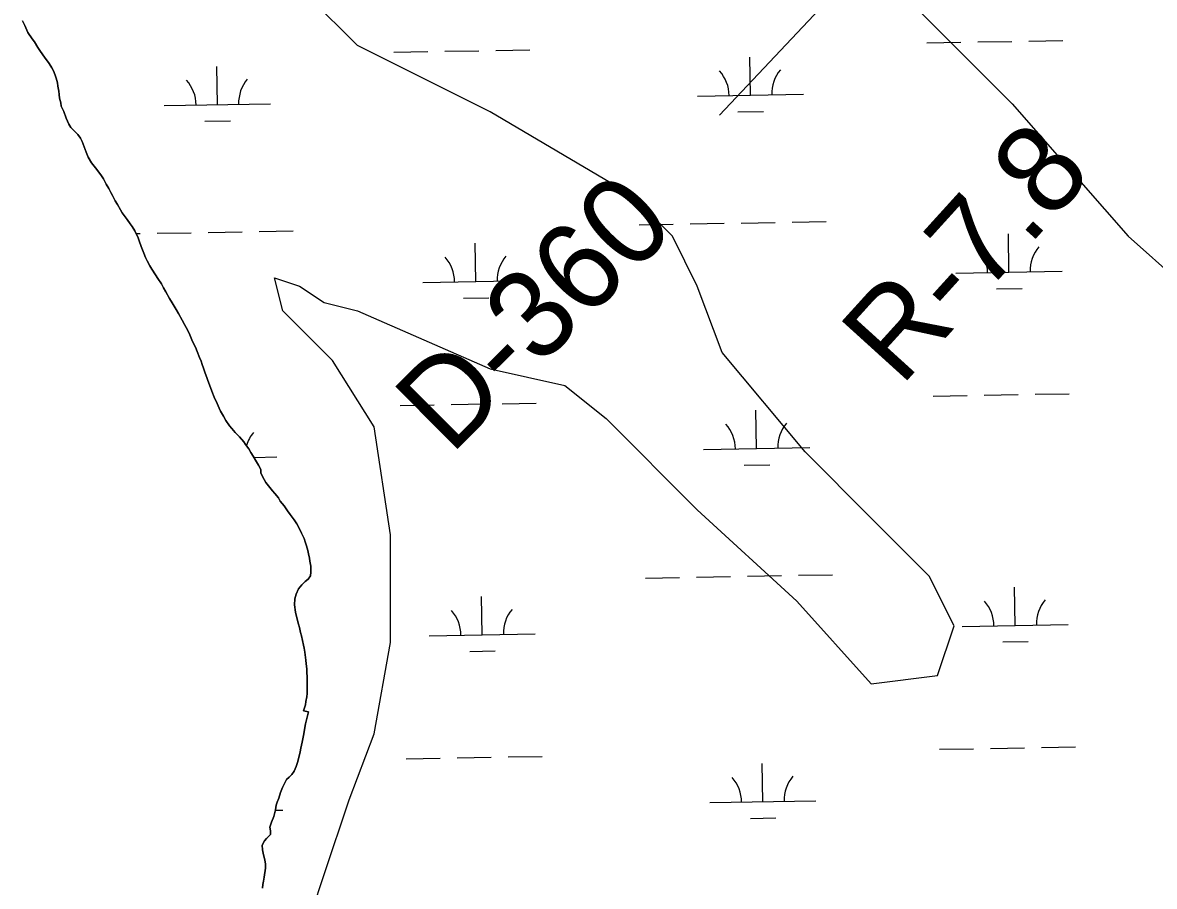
# Model space of a CAD drawing. Extents: x 3903937 to 3942190, y 260677 to 286651.
# Drawn here: x 3922685 to 3923750, y 276234 to 277048 of the extents above; entities that cross this region are included whole.
import ezdxf

# ---------------------------------------------------------------- set-up
doc = ezdxf.new("R2010")
doc.units = 0
for name, color, linetype in [('V-RIVR-RANG', 7, 'Continuous'), ('V-RIVR-RANG-IDEN', 7, 'Continuous'), ('V-SITE-VEGE', 7, 'Continuous'), ('V-TOPO-SHOR', 7, 'Continuous'), ('V-WETL-SWMP', 7, 'Continuous')]:
    doc.layers.add(name, color=color, linetype=linetype)

msp = doc.modelspace()

# ---------------------------------------------------------------- linework, layer by layer
at = {"layer": 'V-RIVR-RANG'}
msp.add_line((3923341.1, 276960.6), (3923889, 277543.5), dxfattribs=at)
at = {"layer": 'V-SITE-VEGE'}
for p, q in [((3923484, 277104.3), (3923616.6, 276971.5)), ((3923000.2, 277026.2), (3922930, 277096.5)), ((3923125.1, 276963.7), (3923000.2, 277026.2)), ((3923257.7, 276885.7), (3923125.1, 276963.7)), ((3923616.6, 276971.5), (3923725.9, 276846.6)), ((3923296.7, 276846.6), (3923257.7, 276885.7)), ((3923320.1, 276799.8), (3923296.7, 276846.6)), ((3923725.9, 276846.6), (3923866.3, 276721.7)), ((3922930, 276776.4), (3922922.2, 276807.6)), ((3922922.2, 276807.6), (3922945.6, 276799.8)), ((3922945.6, 276799.8), (3922969, 276784.2)), ((3923343.5, 276737.3), (3923320.1, 276799.8)), ((3922969, 276784.2), (3923000.2, 276776.4)), ((3922976.8, 276729.5), (3922930, 276776.4)), ((3923000.2, 276776.4), (3923125.1, 276721.7)), ((3923015.8, 276667.1), (3922976.8, 276729.5)), ((3923421.6, 276643.7), (3923343.5, 276737.3)), ((3923125.1, 276721.7), (3923195.3, 276706.1)), ((3923195.3, 276706.1), (3923234.3, 276674.9)), ((3923234.3, 276674.9), (3923320.1, 276589)), ((3923031.4, 276565.6), (3923015.8, 276667.1)), ((3923484, 276581.2), (3923421.6, 276643.7)), ((3923320.1, 276589), (3923413.8, 276503.1)), ((3923538.6, 276526.6), (3923484, 276581.2)), ((3923031.4, 276464.1), (3923031.4, 276565.6)), ((3923562, 276479.7), (3923538.6, 276526.6)), ((3923413.8, 276503.1), (3923484, 276425.1)), ((3923546.4, 276432.9), (3923562, 276479.7)), ((3923015.8, 276378.2), (3923031.4, 276464.1)), ((3923484, 276425.1), (3923546.4, 276432.9)), ((3922992.4, 276315.8), (3923015.8, 276378.2)), ((3922969, 276245.5), (3922992.4, 276315.8)), ((3922945.6, 276175.2), (3922969, 276245.5))]:
    msp.add_line(p, q, dxfattribs=at)
at = {"layer": 'V-TOPO-SHOR'}
for points in [[(3922685, 277049.5), (3922687, 277045), (3922690, 277038.6)], [(3922690, 277038.6), (3922694, 277032.7), (3922696.1, 277029.6), (3922699.3, 277024.4), (3922701.8, 277020.7), (3922705.7, 277015.2), (3922710.1, 277009.4), (3922712.5, 277005.3), (3922714, 277002.5), (3922715.7, 276998.3), (3922716.7, 276995.5), (3922717.7, 276991), (3922718.1, 276988), (3922719.1, 276983.3), (3922719.4, 276980), (3922719.8, 276976.8), (3922720.8, 276972.4), (3922721.4, 276969), (3922723.7, 276964.1), (3922725.9, 276958), (3922728.4, 276952.2), (3922730.4, 276949.2), (3922734.1, 276945.3), (3922736.9, 276942.5), (3922739.6, 276938.9), (3922741.1, 276936), (3922742.9, 276931), (3922744.8, 276925.9), (3922746.8, 276921), (3922749.8, 276915.7), (3922754.8, 276909.5), (3922759.3, 276903.4), (3922761.2, 276900.8), (3922763.6, 276895.8), (3922766.2, 276891.6), (3922768.1, 276887.9), (3922769.5, 276885), (3922772.2, 276880), (3922774.2, 276876.6), (3922777, 276871.6), (3922778.8, 276868.6), (3922781.5, 276864.8), (3922783.3, 276862.3), (3922786.3, 276858.4), (3922788.2, 276855.8), (3922790.5, 276851.7), (3922792, 276848.9), (3922793.5, 276846.2), (3922794.8, 276842.4), (3922796.7, 276837.1), (3922799, 276830.6), (3922800.7, 276826.5), (3922802.2, 276823.6), (3922804.9, 276818.9), (3922806.7, 276815.7), (3922810.2, 276810.4), (3922812.4, 276807), (3922815.6, 276801.8), (3922817.7, 276798.1), (3922819.9, 276794.2), (3922823.3, 276788.1), (3922825.7, 276783.9), (3922829.4, 276777.8), (3922831.7, 276773.8), (3922835.3, 276767.6), (3922837.4, 276763.4), (3922840.4, 276757.9), (3922842.4, 276753.8), (3922845, 276747.5), (3922847.7, 276742.1), (3922849.4, 276738.1), (3922851.6, 276732.4), (3922853, 276728.9), (3922854.1, 276725.8), (3922855.4, 276722.3), (3922856.8, 276717.6), (3922858.3, 276713.7), (3922859.4, 276710.9), (3922861, 276706.7), (3922863.1, 276700.9), (3922865.2, 276695.1), (3922868, 276689.1), (3922870.1, 276684.8), (3922871.4, 276682), (3922874.2, 276677.1), (3922876.2, 276673.2), (3922879.7, 276668.1), (3922881.8, 276665.6), (3922885.2, 276661.8), (3922889.1, 276657.9), (3922893.1, 276653.2), (3922894.9, 276650.7), (3922897.9, 276646.4), (3922899.7, 276643), (3922901.9, 276639.5), (3922905.2, 276634.1), (3922907.2, 276631.1), (3922909.4, 276626.9), (3922909.4, 276623.9), (3922910.8, 276620.5), (3922913.9, 276614.9)], [(3922913.9, 276614.9), (3922916.4, 276611.5), (3922920.2, 276607), (3922922.4, 276604.5), (3922925.8, 276600.3), (3922927.6, 276597.3), (3922931.1, 276592.7), (3922934.5, 276588), (3922936.9, 276584.7), (3922940.6, 276579.5), (3922943.1, 276575.8), (3922946.1, 276570.5), (3922947.6, 276567.1), (3922949.9, 276562.1), (3922951.1, 276558.8), (3922952.3, 276555.2), (3922953.6, 276550.6), (3922954.1, 276547.6), (3922955, 276543.6), (3922955.5, 276540.6), (3922956.2, 276536.1), (3922956.3, 276530.3), (3922955.9, 276527), (3922953.7, 276523.8), (3922951, 276521.4), (3922947.9, 276518.4), (3922944.7, 276514.5), (3922942.4, 276509.7), (3922941.3, 276505.3), (3922941, 276499.5), (3922942, 276492.8), (3922942.9, 276488.6), (3922944.7, 276481.3), (3922945.6, 276478.3), (3922946.6, 276473.5), (3922947.5, 276470.3), (3922948.4, 276465.9), (3922949.5, 276461.7), (3922950.1, 276458.7), (3922950.8, 276455), (3922951.6, 276447.6), (3922952, 276444.1), (3922952.5, 276439.3), (3922952.7, 276436), (3922952.9, 276431.8), (3922952.9, 276425.8), (3922952.9, 276421.9), (3922952.9, 276416.2), (3922952.4, 276412.8), (3922951.7, 276408.5), (3922951.3, 276405.3), (3922949.5, 276399.9), (3922954, 276398.8), (3922952.7, 276392.5), (3922951.2, 276387.5), (3922950.7, 276384), (3922949.8, 276378.2), (3922948.1, 276370.3), (3922946.8, 276364.6), (3922946.2, 276361.1), (3922945.2, 276357), (3922943.8, 276351.1), (3922942.5, 276347.4), (3922940.6, 276343), (3922938.3, 276339.7), (3922936, 276337.4), (3922933.4, 276335), (3922931.6, 276331.4), (3922929.7, 276327.4), (3922927.7, 276322.7), (3922926.1, 276317.6), (3922924.7, 276313.8), (3922923.7, 276310.8), (3922923.1, 276306.6), (3922921.4, 276300.3), (3922919.3, 276294.9), (3922917.8, 276290.2), (3922918.5, 276286.6), (3922918.3, 276283.2), (3922914.7, 276279.5), (3922912.6, 276277.3), (3922910.6, 276273.3), (3922910.9, 276268.9), (3922911.9, 276264.3), (3922912.9, 276259.3), (3922913.6, 276255.4), (3922913.6, 276251.7), (3922912.5, 276243.1), (3922911.8, 276239.4), (3922911, 276236.2), (3922910.8, 276232.7)]]:
    msp.add_lwpolyline(points, dxfattribs=at)
at = {"layer": 'V-WETL-SWMP'}
for p, q in [((3922687, 277045), (3922685, 277049.5)), ((3922690, 277038.6), (3922687, 277045)), ((3922694, 277032.7), (3922690, 277038.6)), ((3922696.1, 277029.6), (3922694, 277032.7)), ((3922699.3, 277024.4), (3922696.1, 277029.6)), ((3923536.4, 277028.7), (3923568.4, 277029.3)), ((3923584.4, 277029.6), (3923616.4, 277030.2)), ((3923632.4, 277030.4), (3923664.3, 277031)), ((3922701.8, 277020.7), (3922699.3, 277024.4)), ((3922705.7, 277015.2), (3922701.8, 277020.7)), ((3922710.1, 277009.4), (3922705.7, 277015.2)), ((3923034.5, 277019.9), (3923066.5, 277020.5)), ((3923082.5, 277020.8), (3923114.5, 277021.3)), ((3923130.5, 277021.6), (3923162.5, 277022.2)), ((3923370.1, 276979.4), (3923369.5, 277015.4)), ((3922712.6, 277005.3), (3922710.1, 277009.4)), ((3922714, 277002.5), (3922712.6, 277005.3)), ((3922868.3, 276970.6), (3922867.7, 277006.5)), ((3922715.7, 276998.3), (3922714, 277002.5)), ((3922716.7, 276995.5), (3922715.7, 276998.3)), ((3922717.7, 276991), (3922716.7, 276995.5)), ((3922718.1, 276988), (3922717.7, 276991)), ((3922719.1, 276983.3), (3922718.1, 276988)), ((3922719.4, 276980), (3922719.1, 276983.3)), ((3922719.8, 276976.8), (3922719.4, 276980)), ((3922720.8, 276972.4), (3922719.8, 276976.8)), ((3922721.4, 276969), (3922720.8, 276972.4)), ((3923320.2, 276978.5), (3923420.1, 276980.3)), ((3922723.7, 276964.1), (3922721.4, 276969)), ((3922725.9, 276957.9), (3922723.7, 276964.1)), ((3922818.3, 276969.7), (3922918.3, 276971.4)), ((3923358.4, 276963.7), (3923382.4, 276964.2)), ((3922728.4, 276952.2), (3922725.9, 276957.9)), ((3922730.4, 276949.2), (3922728.4, 276952.2)), ((3922856.6, 276954.9), (3922880.6, 276955.3)), ((3922734.1, 276945.3), (3922730.4, 276949.2)), ((3922736.9, 276942.5), (3922734.1, 276945.3)), ((3922739.6, 276938.9), (3922736.9, 276942.5)), ((3922741.1, 276936), (3922739.6, 276938.9)), ((3922742.9, 276931), (3922741.1, 276936)), ((3922744.8, 276925.9), (3922742.9, 276931)), ((3922746.8, 276921), (3922744.8, 276925.9)), ((3922749.8, 276915.7), (3922746.8, 276921)), ((3922754.8, 276909.5), (3922749.8, 276915.7)), ((3922759.3, 276903.4), (3922754.8, 276909.5)), ((3922761.2, 276900.8), (3922759.3, 276903.4)), ((3922763.6, 276895.8), (3922761.2, 276900.8)), ((3922766.2, 276891.6), (3922763.6, 276895.8)), ((3922768.1, 276887.9), (3922766.2, 276891.6)), ((3922769.5, 276885), (3922768.1, 276887.9)), ((3922772.2, 276880), (3922769.5, 276885)), ((3922774.2, 276876.6), (3922772.2, 276880)), ((3922777, 276871.6), (3922774.2, 276876.6)), ((3922778.8, 276868.6), (3922777, 276871.6)), ((3922781.5, 276864.8), (3922778.8, 276868.6)), ((3922783.3, 276862.3), (3922781.5, 276864.8)), ((3922786.3, 276858.4), (3922783.3, 276862.3)), ((3922788.2, 276855.8), (3922786.3, 276858.4)), ((3922790.5, 276851.7), (3922788.2, 276855.8)), ((3923265.4, 276857.5), (3923297.4, 276858)), ((3923313.4, 276858.3), (3923345.4, 276858.9)), ((3923361.4, 276859.1), (3923393.4, 276859.7)), ((3923409.4, 276860), (3923441.4, 276860.6)), ((3922792, 276848.9), (3922790.5, 276851.7)), ((3922791.9, 276849.1), (3922795.6, 276849.2)), ((3922793.5, 276846.2), (3922792, 276848.9)), ((3922794.8, 276842.4), (3922793.5, 276846.2)), ((3922811.6, 276849.5), (3922843.6, 276850)), ((3922859.6, 276850.3), (3922891.6, 276850.9)), ((3922907.6, 276851.2), (3922939.6, 276851.7)), ((3923613.6, 276812.8), (3923613, 276848.8)), ((3922796.7, 276837.1), (3922794.8, 276842.4)), ((3922799, 276830.6), (3922796.7, 276837.1)), ((3923111.8, 276804), (3923111.1, 276840)), ((3922800.7, 276826.5), (3922799, 276830.6)), ((3922802.2, 276823.6), (3922800.7, 276826.5)), ((3922804.9, 276818.9), (3922802.2, 276823.6)), ((3922806.7, 276815.7), (3922804.9, 276818.9)), ((3922810.2, 276810.4), (3922806.7, 276815.7)), ((3923563.6, 276812), (3923663.6, 276813.7)), ((3922812.4, 276807), (3922810.2, 276810.4)), ((3922815.6, 276801.8), (3922812.4, 276807)), ((3922817.7, 276798.1), (3922815.6, 276801.8)), ((3923061.8, 276803.1), (3923161.7, 276804.9)), ((3922819.9, 276794.2), (3922817.7, 276798.1)), ((3922823.3, 276788.1), (3922819.9, 276794.2)), ((3923601.9, 276797.2), (3923625.9, 276797.6)), ((3922825.7, 276783.9), (3922823.3, 276788.1)), ((3922829.4, 276777.8), (3922825.7, 276783.9)), ((3923100, 276788.4), (3923124, 276788.8)), ((3922831.7, 276773.8), (3922829.4, 276777.8)), ((3922835.3, 276767.6), (3922831.7, 276773.8)), ((3922837.4, 276763.4), (3922835.3, 276767.6)), ((3922840.4, 276757.9), (3922837.4, 276763.4)), ((3922842.4, 276753.8), (3922840.4, 276757.9)), ((3922845, 276747.5), (3922842.4, 276753.8)), ((3922847.7, 276742.1), (3922845, 276747.5)), ((3922849.4, 276738.1), (3922847.7, 276742.1)), ((3922851.6, 276732.4), (3922849.4, 276738.1)), ((3922853, 276728.9), (3922851.6, 276732.4)), ((3922854.1, 276725.8), (3922853, 276728.9)), ((3922855.4, 276722.3), (3922854.1, 276725.8)), ((3922856.8, 276717.6), (3922855.4, 276722.3)), ((3922858.3, 276713.7), (3922856.8, 276717.6)), ((3922859.4, 276710.9), (3922858.3, 276713.7)), ((3922861, 276706.7), (3922859.4, 276710.9)), ((3922863.1, 276700.9), (3922861, 276706.7)), ((3922865.2, 276695.1), (3922863.1, 276700.9)), ((3923542.2, 276696.1), (3923574.2, 276696.7)), ((3923590.2, 276697), (3923622.2, 276697.5)), ((3923638.2, 276697.8), (3923670.2, 276698.4)), ((3922868, 276689.1), (3922865.2, 276695.1)), ((3922870.1, 276684.8), (3922868, 276689.1)), ((3922871.4, 276682), (3922870.1, 276684.8)), ((3923040.4, 276687.3), (3923072.4, 276687.9)), ((3923088.4, 276688.1), (3923120.4, 276688.7)), ((3923136.4, 276689), (3923168.4, 276689.5)), ((3922874.2, 276677.1), (3922871.4, 276682)), ((3922876.2, 276673.2), (3922874.2, 276677.1)), ((3923376, 276646.8), (3923375.4, 276682.8)), ((3922879.7, 276668.1), (3922876.2, 276673.2)), ((3922881.8, 276665.6), (3922879.7, 276668.1)), ((3922885.2, 276661.8), (3922881.8, 276665.6)), ((3922889.1, 276657.9), (3922885.2, 276661.8)), ((3922893.1, 276653.2), (3922889.1, 276657.9)), ((3922894.9, 276650.7), (3922893.1, 276653.2)), ((3922897.9, 276646.4), (3922894.9, 276650.7)), ((3922899.7, 276643), (3922897.9, 276646.4)), ((3922901.9, 276639.5), (3922899.7, 276643)), ((3923326, 276645.9), (3923426, 276647.6)), ((3922905.2, 276634.1), (3922901.9, 276639.5)), ((3922902.6, 276638.4), (3922924.2, 276638.8)), ((3922907.2, 276631.1), (3922905.2, 276634.1)), ((3923364.3, 276631.1), (3923388.3, 276631.5)), ((3922909.4, 276626.9), (3922907.2, 276631.1)), ((3922909.4, 276623.9), (3922909.4, 276626.9)), ((3922910.8, 276620.5), (3922909.4, 276623.9)), ((3922913.9, 276614.9), (3922910.8, 276620.5)), ((3922916.4, 276611.5), (3922913.9, 276614.9)), ((3922920.2, 276607), (3922916.4, 276611.5)), ((3922922.4, 276604.5), (3922920.2, 276607)), ((3922925.8, 276600.3), (3922922.4, 276604.5)), ((3922927.6, 276597.3), (3922925.8, 276600.3)), ((3922931.1, 276592.7), (3922927.6, 276597.3)), ((3922934.5, 276588), (3922931.1, 276592.7)), ((3922936.9, 276584.7), (3922934.5, 276588)), ((3922940.6, 276579.5), (3922936.9, 276584.7)), ((3922943.1, 276575.8), (3922940.6, 276579.5)), ((3922946.1, 276570.5), (3922943.1, 276575.8)), ((3922947.6, 276567.1), (3922946.1, 276570.5)), ((3922949.9, 276562.1), (3922947.6, 276567.1)), ((3922951.1, 276558.8), (3922949.9, 276562.1)), ((3922952.3, 276555.2), (3922951.1, 276558.8)), ((3922953.6, 276550.6), (3922952.3, 276555.2)), ((3922954.1, 276547.6), (3922953.6, 276550.6)), ((3922955, 276543.6), (3922954.1, 276547.6)), ((3922955.5, 276540.6), (3922955, 276543.6)), ((3922956.2, 276536.1), (3922955.5, 276540.6)), ((3922956.3, 276530.3), (3922956.2, 276536.1)), ((3922953.7, 276523.8), (3922955.9, 276527)), ((3922955.9, 276527), (3922956.3, 276530.3)), ((3923271.3, 276524.8), (3923303.3, 276525.4)), ((3923319.3, 276525.7), (3923351.3, 276526.2)), ((3923367.3, 276526.5), (3923399.3, 276527.1)), ((3923415.3, 276527.4), (3923447.3, 276527.9)), ((3922942.4, 276509.7), (3922944.7, 276514.5)), ((3922944.7, 276514.5), (3922947.9, 276518.4)), ((3922947.9, 276518.4), (3922951, 276521.4)), ((3922951, 276521.4), (3922953.7, 276523.8)), ((3923619.4, 276480.2), (3923618.8, 276516.2)), ((3922941, 276499.5), (3922941.3, 276505.3)), ((3922941.3, 276505.3), (3922942.4, 276509.7)), ((3923117.6, 276471.4), (3923117, 276507.4)), ((3922942, 276492.8), (3922941, 276499.5)), ((3922942.9, 276488.6), (3922942, 276492.8)), ((3922944.7, 276481.3), (3922942.9, 276488.6)), ((3922945.7, 276478.3), (3922944.7, 276481.3)), ((3922946.6, 276473.5), (3922945.7, 276478.3)), ((3922947.5, 276470.3), (3922946.6, 276473.5)), ((3923067.6, 276470.5), (3923167.6, 276472.3)), ((3923569.4, 276479.3), (3923669.4, 276481.1)), ((3922948.4, 276465.9), (3922947.5, 276470.3)), ((3922949.5, 276461.7), (3922948.4, 276465.9)), ((3922950.1, 276458.7), (3922949.5, 276461.7)), ((3923607.7, 276464.6), (3923631.7, 276465)), ((3922950.8, 276455), (3922950.1, 276458.7)), ((3922951.6, 276447.6), (3922950.8, 276455)), ((3923105.9, 276455.7), (3923129.9, 276456.2)), ((3922952, 276444.1), (3922951.6, 276447.6)), ((3922952.5, 276439.3), (3922952, 276444.1)), ((3922952.7, 276436), (3922952.5, 276439.3)), ((3922952.9, 276431.8), (3922952.7, 276436)), ((3922952.9, 276425.8), (3922952.9, 276431.8)), ((3922952.9, 276421.9), (3922952.9, 276425.8)), ((3922952.9, 276416.2), (3922952.9, 276421.9)), ((3922951.3, 276405.3), (3922951.7, 276408.5)), ((3922951.7, 276408.5), (3922952.4, 276412.8)), ((3922952.4, 276412.8), (3922952.9, 276416.2)), ((3922949.5, 276399.9), (3922951.3, 276405.3)), ((3922954, 276398.8), (3922949.5, 276399.9)), ((3922952.7, 276392.5), (3922954, 276398.8)), ((3922950.7, 276384), (3922951.2, 276387.5)), ((3922951.2, 276387.5), (3922952.7, 276392.5)), ((3922948.1, 276370.3), (3922949.8, 276378.2)), ((3922949.8, 276378.2), (3922950.7, 276384)), ((3922946.8, 276364.6), (3922948.1, 276370.3)), ((3923644.1, 276365.2), (3923676.1, 276365.8)), ((3922943.8, 276351.1), (3922945.2, 276357)), ((3922945.2, 276357), (3922946.2, 276361.1)), ((3922946.2, 276361.1), (3922946.8, 276364.6)), ((3923046.2, 276354.7), (3923078.2, 276355.2)), ((3923094.2, 276355.5), (3923126.2, 276356.1)), ((3923142.2, 276356.4), (3923174.2, 276356.9)), ((3923548.1, 276363.5), (3923580.1, 276364.1)), ((3923596.1, 276364.3), (3923628.1, 276364.9)), ((3922940.6, 276343), (3922942.5, 276347.4)), ((3922942.5, 276347.4), (3922943.8, 276351.1)), ((3923381.9, 276314.1), (3923381.2, 276350.1)), ((3922931.6, 276331.4), (3922933.4, 276335)), ((3922933.4, 276335), (3922936, 276337.4)), ((3922936, 276337.4), (3922938.3, 276339.7)), ((3922938.3, 276339.7), (3922940.6, 276343)), ((3922926.1, 276317.6), (3922927.7, 276322.7)), ((3922927.7, 276322.7), (3922929.7, 276327.4)), ((3922929.7, 276327.4), (3922931.6, 276331.4)), ((3922923.7, 276310.8), (3922924.7, 276313.8)), ((3922924.7, 276313.8), (3922926.1, 276317.6)), ((3923331.9, 276313.3), (3923431.8, 276315)), ((3922921.4, 276300.3), (3922923.1, 276306.6)), ((3922922.9, 276306.1), (3922930, 276306.2)), ((3922923.1, 276306.6), (3922923.7, 276310.8)), ((3922917.8, 276290.2), (3922919.3, 276294.9)), ((3922919.3, 276294.9), (3922921.4, 276300.3)), ((3923370.1, 276298.5), (3923394.1, 276298.9)), ((3922914.7, 276279.5), (3922918.3, 276283.2)), ((3922918.5, 276286.6), (3922917.8, 276290.2)), ((3922918.3, 276283.2), (3922918.5, 276286.6)), ((3922910.6, 276273.3), (3922912.6, 276277.3)), ((3922910.9, 276268.9), (3922910.6, 276273.3)), ((3922912.6, 276277.3), (3922914.7, 276279.5)), ((3922911.9, 276264.3), (3922910.9, 276268.9)), ((3922912.9, 276259.3), (3922911.9, 276264.3)), ((3922913.6, 276255.4), (3922912.9, 276259.3)), ((3922912.5, 276243.1), (3922913.6, 276251.7)), ((3922913.6, 276251.7), (3922913.6, 276255.4)), ((3922911, 276236.2), (3922911.8, 276239.4)), ((3922911.8, 276239.4), (3922912.5, 276243.1)), ((3922910.8, 276232.7), (3922911, 276236.2))]:
    msp.add_line(p, q, dxfattribs=at)
for centre, start, end in [((3922923.5, 276972), 140.2366, 181.7802), ((3923314.9, 276978.9), 0.2366, 41.7802), ((3923425.4, 276980.8), 140.2366, 181.7802), ((3922813.1, 276970.1), 0.2366, 41.7802), ((3923558.3, 276812.3), 0.2366, 41.7802), ((3923668.8, 276814.3), 140.2366, 181.7802), ((3923056.5, 276803.5), 0.2366, 41.7802), ((3923167, 276805.4), 140.2366, 181.7802), ((3923320.8, 276646.3), 0.2366, 41.7802), ((3923431.2, 276648.2), 140.2366, 181.7802), ((3922929.4, 276639.4), 140.2366, 163.0254), ((3923674.7, 276481.7), 140.2366, 181.7802), ((3923062.4, 276470.9), 0.2366, 41.7802), ((3923172.8, 276472.8), 140.2366, 181.7802), ((3923564.2, 276479.7), 0.2366, 41.7802), ((3923326.6, 276313.6), 0.2366, 41.7802), ((3923437.1, 276315.6), 140.2366, 181.7802)]:
    msp.add_arc(centre, 35.2, start, end, dxfattribs=at)

# ---------------------------------------------------------------- texts
at = {"layer": 'V-RIVR-RANG-IDEN'}
for s, rotation, p in [('R-7.8', 47.7829, (3923511.7, 276704.2)), ('D-360', 44.9188, (3923088, 276639.9))]:
    msp.add_text(s, height=83, rotation=rotation, dxfattribs=at).set_placement(p)

doc.saveas('drawing.dxf')
